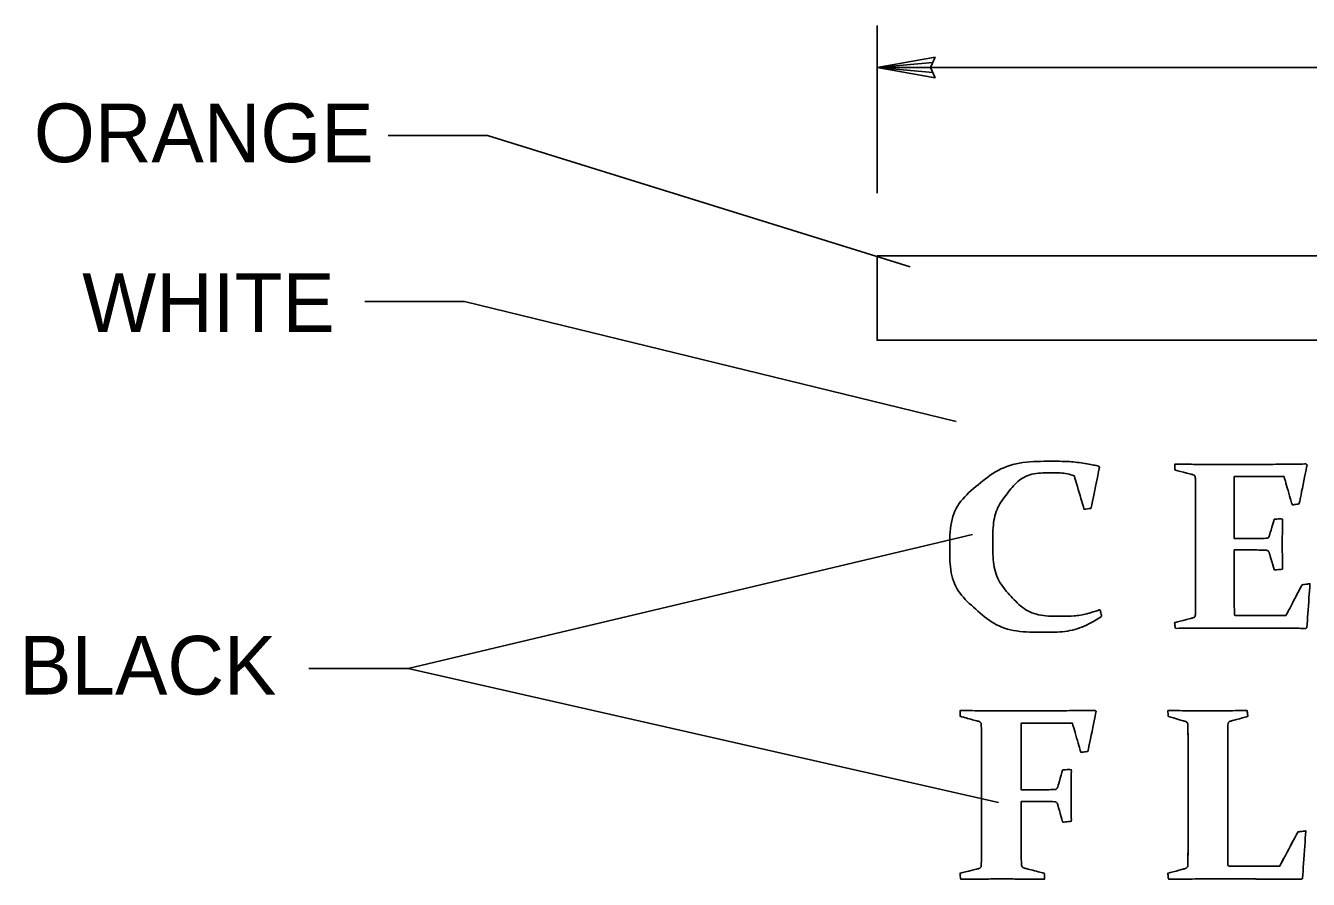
# Model space of a CAD drawing. Extents: x 60714 to 61343, y 7599 to 7998.
# Drawn here: x 60919.9 to 60981.2, y 7950.5 to 7991.3 of the extents above; entities that cross this region are included whole.
import ezdxf

# ---------------------------------------------------------------- set-up
doc = ezdxf.new("R2010")
doc.units = 0
for name, color, linetype in [('2', 7, 'Continuous'), ('21', 7, 'Continuous'), ('Default', 7, 'Continuous'), ('SignPanel', 7, 'Continuous')]:
    doc.layers.add(name, color=color, linetype=linetype)

# ---------------------------------------------------------------- blocks, each defined once
blk = doc.blocks.new('block 5')
at = {"layer": 'Default'}
for points in [[(397.18, -471.19), (397.18, -471.19), (394.77, -471.59), (394.77, -471.59), (394.77, -471.59), (391.44, -459.01), (391.44, -459.01), (389.13, -458.28), (386.63, -457.91), (383.94, -457.91), (377.49, -457.91), (372.49, -460.33), (368.96, -465.17), (365.42, -470), (363.66, -476.33), (363.66, -484.16), (363.66, -492.52), (365.74, -499.18), (369.9, -504.14), (374.06, -509.11), (379.84, -511.59), (387.23, -511.59), (391.35, -511.59), (395.69, -510.76), (400.24, -509.09), (400.24, -509.09), (400.81, -511.59), (400.81, -511.59), (394.97, -515.56), (388.37, -517.55), (381.01, -517.55), (371.46, -517.55), (363.74, -514.67), (357.85, -508.92), (351.96, -503.16), (349.02, -495.58), (349.02, -486.18), (349.02, -476.16), (352.25, -468.23), (358.71, -462.38), (365.16, -456.54), (373.59, -453.62), (383.99, -453.62), (389.13, -453.62), (394.39, -454.22), (399.76, -455.42), (399.76, -455.42), (400.03, -455.86), (400.03, -455.86), (400.03, -455.86), (397.18, -471.19), (397.18, -471.19)], [(397.18, -471.19), (397.18, -471.19), (394.77, -471.59), (394.77, -471.59), (394.77, -471.59), (391.44, -459.01), (391.44, -459.01), (389.13, -458.28), (386.63, -457.91), (383.94, -457.91), (377.49, -457.91), (372.49, -460.33), (368.96, -465.17), (365.42, -470), (363.66, -476.33), (363.66, -484.16), (363.66, -492.52), (365.74, -499.18), (369.9, -504.14), (374.06, -509.11), (379.84, -511.59), (387.23, -511.59), (391.35, -511.59), (395.69, -510.76), (400.24, -509.09), (400.24, -509.09), (400.81, -511.59), (400.81, -511.59), (394.97, -515.56), (388.37, -517.55), (381.01, -517.55), (371.46, -517.55), (363.74, -514.67), (357.85, -508.92), (351.96, -503.16), (349.02, -495.58), (349.02, -486.18), (349.02, -476.16), (352.25, -468.23), (358.71, -462.38), (365.16, -456.54), (373.59, -453.62), (383.99, -453.62), (389.13, -453.62), (394.39, -454.22), (399.76, -455.42), (399.76, -455.42), (400.03, -455.86), (400.03, -455.86), (400.03, -455.86), (397.18, -471.19), (397.18, -471.19)], [(437.3, -454.8), (437.3, -454.8), (448.38, -454.8), (448.38, -454.8), (455.48, -454.8), (462.84, -454.75), (470.47, -454.63), (470.47, -454.63), (470.77, -454.98), (470.77, -454.98), (470.77, -454.98), (468.06, -469.57), (468.06, -469.57), (468.06, -469.57), (465.69, -469.92), (465.69, -469.92), (465.69, -469.92), (462.89, -459.27), (462.89, -459.27), (462.89, -459.27), (445.93, -459.27), (445.93, -459.27), (445.93, -459.27), (445.93, -482.54), (445.93, -482.54), (445.93, -482.54), (448.3, -482.54), (448.3, -482.54), (450.84, -482.54), (453.57, -482.51), (456.49, -482.45), (457.25, -482.42), (457.75, -482.03), (457.98, -481.27), (457.98, -481.27), (459.56, -475.27), (459.56, -475.27), (459.56, -475.27), (462.45, -475.13), (462.45, -475.13), (462.36, -479.37), (462.32, -482.54), (462.32, -484.64), (462.32, -486.69), (462.36, -489.81), (462.45, -494.02), (462.45, -494.02), (459.56, -494.24), (459.56, -494.24), (459.56, -494.24), (457.94, -488.06), (457.94, -488.06), (457.7, -487.27), (457.25, -486.86), (456.58, -486.83), (453.6, -486.78), (450.82, -486.75), (448.25, -486.75), (448.25, -486.75), (445.93, -486.75), (445.93, -486.75), (445.93, -486.75), (445.93, -501.78), (445.93, -501.78), (445.93, -504.99), (445.96, -508.17), (446.02, -511.33), (446.02, -511.33), (463.54, -511.33), (463.54, -511.33), (463.54, -511.33), (469.06, -499.8), (469.06, -499.8), (469.06, -499.8), (471.74, -499.41), (471.74, -499.41), (471.74, -499.41), (470.69, -515.8), (470.69, -515.8), (470.69, -515.8), (470.38, -516.1), (470.38, -516.1), (463.11, -516.02), (456.02, -515.97), (449.13, -515.97), (449.13, -515.97), (437.52, -515.97), (437.52, -515.97), (433.75, -515.97), (429.86, -516.02), (425.86, -516.1), (425.86, -516.1), (425.64, -513.91), (425.64, -513.91), (425.64, -513.91), (431.51, -512.29), (431.51, -512.29), (432.24, -512.09), (432.64, -511.64), (432.7, -510.93), (432.73, -509.77), (432.75, -508.46), (432.76, -507.01), (432.78, -505.57), (432.78, -503.97), (432.78, -502.21), (432.78, -502.21), (432.78, -467.29), (432.78, -467.29), (432.78, -465.83), (432.78, -464.5), (432.76, -463.3), (432.75, -462.11), (432.73, -461.01), (432.7, -460.02), (432.67, -459.26), (432.32, -458.78), (431.64, -458.57), (431.64, -458.57), (425.77, -456.86), (425.77, -456.86), (425.77, -456.86), (425.64, -454.63), (425.64, -454.63), (429.73, -454.75), (433.62, -454.8), (437.3, -454.8)], [(437.3, -454.8), (437.3, -454.8), (448.38, -454.8), (448.38, -454.8), (455.48, -454.8), (462.84, -454.75), (470.47, -454.63), (470.47, -454.63), (470.77, -454.98), (470.77, -454.98), (470.77, -454.98), (468.06, -469.57), (468.06, -469.57), (468.06, -469.57), (465.69, -469.92), (465.69, -469.92), (465.69, -469.92), (462.89, -459.27), (462.89, -459.27), (462.89, -459.27), (445.93, -459.27), (445.93, -459.27), (445.93, -459.27), (445.93, -482.54), (445.93, -482.54), (445.93, -482.54), (448.3, -482.54), (448.3, -482.54), (450.84, -482.54), (453.57, -482.51), (456.49, -482.45), (457.25, -482.42), (457.75, -482.03), (457.98, -481.27), (457.98, -481.27), (459.56, -475.27), (459.56, -475.27), (459.56, -475.27), (462.45, -475.13), (462.45, -475.13), (462.36, -479.37), (462.32, -482.54), (462.32, -484.64), (462.32, -486.69), (462.36, -489.81), (462.45, -494.02), (462.45, -494.02), (459.56, -494.24), (459.56, -494.24), (459.56, -494.24), (457.94, -488.06), (457.94, -488.06), (457.7, -487.27), (457.25, -486.86), (456.58, -486.83), (453.6, -486.78), (450.82, -486.75), (448.25, -486.75), (448.25, -486.75), (445.93, -486.75), (445.93, -486.75), (445.93, -486.75), (445.93, -501.78), (445.93, -501.78), (445.93, -504.99), (445.96, -508.17), (446.02, -511.33), (446.02, -511.33), (463.54, -511.33), (463.54, -511.33), (463.54, -511.33), (469.06, -499.8), (469.06, -499.8), (469.06, -499.8), (471.74, -499.41), (471.74, -499.41), (471.74, -499.41), (470.69, -515.8), (470.69, -515.8), (470.69, -515.8), (470.38, -516.1), (470.38, -516.1), (463.11, -516.02), (456.02, -515.97), (449.13, -515.97), (449.13, -515.97), (437.52, -515.97), (437.52, -515.97), (433.75, -515.97), (429.86, -516.02), (425.86, -516.1), (425.86, -516.1), (425.64, -513.91), (425.64, -513.91), (425.64, -513.91), (431.51, -512.29), (431.51, -512.29), (432.24, -512.09), (432.64, -511.64), (432.7, -510.93), (432.73, -509.77), (432.75, -508.46), (432.76, -507.01), (432.78, -505.57), (432.78, -503.97), (432.78, -502.21), (432.78, -502.21), (432.78, -467.29), (432.78, -467.29), (432.78, -465.83), (432.78, -464.5), (432.76, -463.3), (432.75, -462.11), (432.73, -461.01), (432.7, -460.02), (432.67, -459.26), (432.32, -458.78), (431.64, -458.57), (431.64, -458.57), (425.77, -456.86), (425.77, -456.86), (425.77, -456.86), (425.64, -454.63), (425.64, -454.63), (429.73, -454.75), (433.62, -454.8), (437.3, -454.8)]]:
    blk.add_open_spline(points, degree=3, dxfattribs=at)
blk = doc.blocks.new('block 6')
at = {"layer": 'Default'}
blk.add_open_spline([(836.58, -467.12), (836.58, -467.12), (836.58, -501.78), (836.58, -501.78), (836.58, -504.99), (836.61, -508.17), (836.67, -511.33), (836.67, -511.33), (853.81, -511.33), (853.81, -511.33), (853.81, -511.33), (859.81, -498.88), (859.81, -498.88), (859.81, -498.88), (862.48, -498.49), (862.48, -498.49), (862.48, -498.49), (861.39, -515.8), (861.39, -515.8), (861.39, -515.8), (861.08, -516.1), (861.08, -516.1), (853.86, -516.02), (846.81, -515.97), (839.91, -515.97), (839.91, -515.97), (829.05, -515.97), (829.05, -515.97), (824.7, -515.97), (820.66, -516.02), (816.95, -516.1), (816.95, -516.1), (816.74, -513.91), (816.74, -513.91), (816.74, -513.91), (822.17, -512.29), (822.17, -512.29), (822.9, -512.09), (823.29, -511.64), (823.35, -510.93), (823.38, -509.77), (823.4, -508.46), (823.42, -507.01), (823.43, -505.57), (823.44, -503.97), (823.44, -502.21), (823.44, -502.21), (823.44, -467.29), (823.44, -467.29), (823.44, -465.83), (823.43, -464.5), (823.42, -463.3), (823.4, -462.11), (823.38, -461.01), (823.35, -460.02), (823.32, -459.26), (822.97, -458.78), (822.3, -458.57), (822.3, -458.57), (816.87, -456.86), (816.87, -456.86), (816.87, -456.86), (816.74, -454.63), (816.74, -454.63), (820.5, -454.75), (824.86, -454.8), (829.79, -454.8), (834.88, -454.8), (839.29, -454.75), (843.03, -454.63), (843.03, -454.63), (843.25, -456.86), (843.25, -456.86), (843.25, -456.86), (837.81, -458.48), (837.81, -458.48), (837.11, -458.66), (836.73, -459.1), (836.67, -459.8), (836.64, -460.85), (836.62, -462.35), (836.6, -464.29), (836.59, -466.23), (836.58, -467.17), (836.58, -467.12)], degree=3, dxfattribs=at)
blk.add_open_spline([(836.58, -467.12), (836.58, -467.12), (836.58, -501.78), (836.58, -501.78), (836.58, -504.99), (836.61, -508.17), (836.67, -511.33), (836.67, -511.33), (853.81, -511.33), (853.81, -511.33), (853.81, -511.33), (859.81, -498.88), (859.81, -498.88), (859.81, -498.88), (862.48, -498.49), (862.48, -498.49), (862.48, -498.49), (861.39, -515.8), (861.39, -515.8), (861.39, -515.8), (861.08, -516.1), (861.08, -516.1), (853.86, -516.02), (846.81, -515.97), (839.91, -515.97), (839.91, -515.97), (829.05, -515.97), (829.05, -515.97), (824.7, -515.97), (820.66, -516.02), (816.95, -516.1), (816.95, -516.1), (816.74, -513.91), (816.74, -513.91), (816.74, -513.91), (822.17, -512.29), (822.17, -512.29), (822.9, -512.09), (823.29, -511.64), (823.35, -510.93), (823.38, -509.77), (823.4, -508.46), (823.42, -507.01), (823.43, -505.57), (823.44, -503.97), (823.44, -502.21), (823.44, -502.21), (823.44, -467.29), (823.44, -467.29), (823.44, -465.83), (823.43, -464.5), (823.42, -463.3), (823.4, -462.11), (823.38, -461.01), (823.35, -460.02), (823.32, -459.26), (822.97, -458.78), (822.3, -458.57), (822.3, -458.57), (816.87, -456.86), (816.87, -456.86), (816.87, -456.86), (816.74, -454.63), (816.74, -454.63), (820.5, -454.75), (824.86, -454.8), (829.79, -454.8), (834.88, -454.8), (839.29, -454.75), (843.03, -454.63), (843.03, -454.63), (843.25, -456.86), (843.25, -456.86), (843.25, -456.86), (837.81, -458.48), (837.81, -458.48), (837.11, -458.66), (836.73, -459.1), (836.67, -459.8), (836.64, -460.85), (836.62, -462.35), (836.6, -464.29), (836.59, -466.23), (836.58, -467.17), (836.58, -467.12)], degree=3, dxfattribs=at)

msp = doc.modelspace()

# ---------------------------------------------------------------- linework, layer by layer
at = {"layer": '2'}
for p, q in [((60960.568, 7983.258), (60960.568, 7991.258)), ((60960.568, 7989.258), (61040.577, 7989.258)), ((60937.206, 7986.017), (60941.956, 7986.017)), ((60962.148, 7979.738), (60941.956, 7986.017)), ((60936.099, 7978.08), (60940.849, 7978.08)), ((60940.849, 7978.08), (60964.348, 7972.35)), ((60938.169, 7960.541), (60965.128, 7966.944)), ((60933.419, 7960.541), (60938.169, 7960.541)), ((60938.169, 7960.541), (60966.372, 7954.138))]:
    msp.add_line(p, q, dxfattribs=at)
at = {"layer": '21'}
for p, q in [((60960.568, 7989.258), (60963.337, 7989.746)), ((60960.568, 7989.258), (60963.224, 7989.49)), ((60963.125, 7989.258), (60963.337, 7989.746)), ((60960.568, 7989.258), (60963.336, 7988.769)), ((60960.568, 7989.258), (60963.226, 7989.026)), ((60963.336, 7988.769), (60963.125, 7989.258))]:
    msp.add_line(p, q, dxfattribs=at)
at = {"layer": 'SignPanel'}
msp.add_lwpolyline([(60960.568, 7980.258), (61040.577, 7980.258), (61040.577, 7976.231), (60960.568, 7976.231), (60960.568, 7980.258)], dxfattribs=at)
for points in [[(60967.45, 7954.194), (60967.45, 7954.194), (60967.45, 7952.295), (60967.45, 7952.295), (60967.45, 7951.842), (60967.455, 7951.472), (60967.463, 7951.184), (60967.467, 7951.091), (60967.522, 7951.03), (60967.627, 7950.999), (60967.627, 7950.999), (60968.555, 7950.758), (60968.555, 7950.758), (60968.555, 7950.758), (60968.574, 7950.47), (60968.574, 7950.47), (60967.922, 7950.482), (60967.24, 7950.487), (60966.529, 7950.487), (60965.8, 7950.487), (60965.144, 7950.482), (60964.559, 7950.47), (60964.559, 7950.47), (60964.527, 7950.758), (60964.527, 7950.758), (60964.527, 7950.758), (60965.373, 7950.971), (60965.373, 7950.971), (60965.483, 7951.001), (60965.54, 7951.061), (60965.544, 7951.149), (60965.552, 7951.46), (60965.556, 7951.842), (60965.556, 7952.295), (60965.556, 7952.295), (60965.556, 7956.882), (60965.556, 7956.882), (60965.556, 7957.073), (60965.555, 7957.248), (60965.553, 7957.405), (60965.551, 7957.563), (60965.548, 7957.707), (60965.544, 7957.837), (60965.54, 7957.937), (60965.489, 7958), (60965.392, 7958.027), (60965.392, 7958.027), (60964.546, 7958.251), (60964.546, 7958.251), (60964.546, 7958.251), (60964.527, 7958.545), (60964.527, 7958.545), (60965.116, 7958.53), (60965.676, 7958.522), (60966.206, 7958.522), (60966.206, 7958.522), (60967.804, 7958.522), (60967.804, 7958.522), (60968.827, 7958.522), (60969.888, 7958.53), (60970.986, 7958.545), (60970.986, 7958.545), (60971.03, 7958.499), (60971.03, 7958.499), (60971.03, 7958.499), (60970.639, 7956.582), (60970.639, 7956.582), (60970.639, 7956.582), (60970.298, 7956.536), (60970.298, 7956.536), (60970.298, 7956.536), (60969.894, 7957.935), (60969.894, 7957.935), (60969.894, 7957.935), (60967.45, 7957.935), (60967.45, 7957.935), (60967.45, 7957.935), (60967.45, 7954.746), (60967.45, 7954.746), (60967.45, 7954.746), (60967.81, 7954.746), (60967.81, 7954.746), (60968.181, 7954.746), (60968.574, 7954.75), (60968.991, 7954.758), (60969.105, 7954.762), (60969.176, 7954.814), (60969.206, 7954.913), (60969.206, 7954.913), (60969.433, 7955.702), (60969.433, 7955.702), (60969.433, 7955.702), (60969.85, 7955.719), (60969.85, 7955.719), (60969.837, 7955.163), (60969.831, 7954.746), (60969.831, 7954.47), (60969.831, 7954.202), (60969.837, 7953.791), (60969.85, 7953.238), (60969.85, 7953.238), (60969.433, 7953.204), (60969.433, 7953.204), (60969.433, 7953.204), (60969.199, 7954.021), (60969.199, 7954.021), (60969.17, 7954.121), (60969.105, 7954.175), (60969.004, 7954.182), (60968.578, 7954.19), (60968.179, 7954.194), (60967.804, 7954.194), (60967.804, 7954.194), (60967.45, 7954.194), (60967.45, 7954.194)], [(60967.45, 7954.194), (60967.45, 7954.194), (60967.45, 7952.295), (60967.45, 7952.295), (60967.45, 7951.842), (60967.455, 7951.472), (60967.463, 7951.184), (60967.467, 7951.091), (60967.522, 7951.03), (60967.627, 7950.999), (60967.627, 7950.999), (60968.555, 7950.758), (60968.555, 7950.758), (60968.555, 7950.758), (60968.574, 7950.47), (60968.574, 7950.47), (60967.922, 7950.482), (60967.24, 7950.487), (60966.529, 7950.487), (60965.8, 7950.487), (60965.144, 7950.482), (60964.559, 7950.47), (60964.559, 7950.47), (60964.527, 7950.758), (60964.527, 7950.758), (60964.527, 7950.758), (60965.373, 7950.971), (60965.373, 7950.971), (60965.483, 7951.001), (60965.54, 7951.061), (60965.544, 7951.149), (60965.552, 7951.46), (60965.556, 7951.842), (60965.556, 7952.295), (60965.556, 7952.295), (60965.556, 7956.882), (60965.556, 7956.882), (60965.556, 7957.073), (60965.555, 7957.248), (60965.553, 7957.405), (60965.551, 7957.563), (60965.548, 7957.707), (60965.544, 7957.837), (60965.54, 7957.937), (60965.489, 7958), (60965.392, 7958.027), (60965.392, 7958.027), (60964.546, 7958.251), (60964.546, 7958.251), (60964.546, 7958.251), (60964.527, 7958.545), (60964.527, 7958.545), (60965.116, 7958.53), (60965.676, 7958.522), (60966.206, 7958.522), (60966.206, 7958.522), (60967.804, 7958.522), (60967.804, 7958.522), (60968.827, 7958.522), (60969.888, 7958.53), (60970.986, 7958.545), (60970.986, 7958.545), (60971.03, 7958.499), (60971.03, 7958.499), (60971.03, 7958.499), (60970.639, 7956.582), (60970.639, 7956.582), (60970.639, 7956.582), (60970.298, 7956.536), (60970.298, 7956.536), (60970.298, 7956.536), (60969.894, 7957.935), (60969.894, 7957.935), (60969.894, 7957.935), (60967.45, 7957.935), (60967.45, 7957.935), (60967.45, 7957.935), (60967.45, 7954.746), (60967.45, 7954.746), (60967.45, 7954.746), (60967.81, 7954.746), (60967.81, 7954.746), (60968.181, 7954.746), (60968.574, 7954.75), (60968.991, 7954.758), (60969.105, 7954.762), (60969.176, 7954.814), (60969.206, 7954.913), (60969.206, 7954.913), (60969.433, 7955.702), (60969.433, 7955.702), (60969.433, 7955.702), (60969.85, 7955.719), (60969.85, 7955.719), (60969.837, 7955.163), (60969.831, 7954.746), (60969.831, 7954.47), (60969.831, 7954.202), (60969.837, 7953.791), (60969.85, 7953.238), (60969.85, 7953.238), (60969.433, 7953.204), (60969.433, 7953.204), (60969.433, 7953.204), (60969.199, 7954.021), (60969.199, 7954.021), (60969.17, 7954.121), (60969.105, 7954.175), (60969.004, 7954.182), (60968.578, 7954.19), (60968.179, 7954.194), (60967.804, 7954.194), (60967.804, 7954.194), (60967.45, 7954.194), (60967.45, 7954.194)], [(60977.316, 7956.905), (60977.316, 7956.905), (60977.316, 7952.352), (60977.316, 7952.352), (60977.316, 7951.93), (60977.32, 7951.512), (60977.329, 7951.097), (60977.329, 7951.097), (60979.798, 7951.097), (60979.798, 7951.097), (60979.798, 7951.097), (60980.662, 7952.732), (60980.662, 7952.732), (60980.662, 7952.732), (60981.047, 7952.784), (60981.047, 7952.784), (60981.047, 7952.784), (60980.89, 7950.51), (60980.89, 7950.51), (60980.89, 7950.51), (60980.845, 7950.47), (60980.845, 7950.47), (60979.806, 7950.482), (60978.789, 7950.487), (60977.796, 7950.487), (60977.796, 7950.487), (60976.23, 7950.487), (60976.23, 7950.487), (60975.603, 7950.487), (60975.022, 7950.482), (60974.488, 7950.47), (60974.488, 7950.47), (60974.456, 7950.758), (60974.456, 7950.758), (60974.456, 7950.758), (60975.239, 7950.971), (60975.239, 7950.971), (60975.344, 7950.998), (60975.401, 7951.057), (60975.409, 7951.149), (60975.414, 7951.303), (60975.417, 7951.474), (60975.419, 7951.664), (60975.421, 7951.854), (60975.422, 7952.064), (60975.422, 7952.295), (60975.422, 7952.295), (60975.422, 7956.882), (60975.422, 7956.882), (60975.422, 7957.073), (60975.421, 7957.248), (60975.419, 7957.405), (60975.417, 7957.563), (60975.414, 7957.707), (60975.409, 7957.837), (60975.405, 7957.937), (60975.355, 7958), (60975.258, 7958.027), (60975.258, 7958.027), (60974.475, 7958.251), (60974.475, 7958.251), (60974.475, 7958.251), (60974.456, 7958.545), (60974.456, 7958.545), (60974.999, 7958.53), (60975.626, 7958.522), (60976.338, 7958.522), (60977.07, 7958.522), (60977.706, 7958.53), (60978.244, 7958.545), (60978.244, 7958.545), (60978.276, 7958.251), (60978.276, 7958.251), (60978.276, 7958.251), (60977.493, 7958.038), (60977.493, 7958.038), (60977.392, 7958.015), (60977.337, 7957.958), (60977.329, 7957.866), (60977.325, 7957.728), (60977.321, 7957.531), (60977.319, 7957.276), (60977.317, 7957.021), (60977.316, 7956.897), (60977.316, 7956.905)], [(60977.316, 7956.905), (60977.316, 7956.905), (60977.316, 7952.352), (60977.316, 7952.352), (60977.316, 7951.93), (60977.32, 7951.512), (60977.329, 7951.097), (60977.329, 7951.097), (60979.798, 7951.097), (60979.798, 7951.097), (60979.798, 7951.097), (60980.662, 7952.732), (60980.662, 7952.732), (60980.662, 7952.732), (60981.047, 7952.784), (60981.047, 7952.784), (60981.047, 7952.784), (60980.89, 7950.51), (60980.89, 7950.51), (60980.89, 7950.51), (60980.845, 7950.47), (60980.845, 7950.47), (60979.806, 7950.482), (60978.789, 7950.487), (60977.796, 7950.487), (60977.796, 7950.487), (60976.23, 7950.487), (60976.23, 7950.487), (60975.603, 7950.487), (60975.022, 7950.482), (60974.488, 7950.47), (60974.488, 7950.47), (60974.456, 7950.758), (60974.456, 7950.758), (60974.456, 7950.758), (60975.239, 7950.971), (60975.239, 7950.971), (60975.344, 7950.998), (60975.401, 7951.057), (60975.409, 7951.149), (60975.414, 7951.303), (60975.417, 7951.474), (60975.419, 7951.664), (60975.421, 7951.854), (60975.422, 7952.064), (60975.422, 7952.295), (60975.422, 7952.295), (60975.422, 7956.882), (60975.422, 7956.882), (60975.422, 7957.073), (60975.421, 7957.248), (60975.419, 7957.405), (60975.417, 7957.563), (60975.414, 7957.707), (60975.409, 7957.837), (60975.405, 7957.937), (60975.355, 7958), (60975.258, 7958.027), (60975.258, 7958.027), (60974.475, 7958.251), (60974.475, 7958.251), (60974.475, 7958.251), (60974.456, 7958.545), (60974.456, 7958.545), (60974.999, 7958.53), (60975.626, 7958.522), (60976.338, 7958.522), (60977.07, 7958.522), (60977.706, 7958.53), (60978.244, 7958.545), (60978.244, 7958.545), (60978.276, 7958.251), (60978.276, 7958.251), (60978.276, 7958.251), (60977.493, 7958.038), (60977.493, 7958.038), (60977.392, 7958.015), (60977.337, 7957.958), (60977.329, 7957.866), (60977.325, 7957.728), (60977.321, 7957.531), (60977.319, 7957.276), (60977.317, 7957.021), (60977.316, 7956.897), (60977.316, 7956.905)]]:
    msp.add_open_spline(points, degree=3, dxfattribs=at)

# ---------------------------------------------------------------- block references
for name, p, xscale, yscale, rotation in [('block 5', (60915.109, 8028.418), 0.14019599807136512, 0.1278006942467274, -6.923017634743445e-08), ('block 6', (60856.795, 8018.26), 0.14406434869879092, 0.13134966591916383, -6.922538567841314e-08)]:
    msp.add_blockref(name, p, dxfattribs=dict(at, xscale=xscale, yscale=yscale, rotation=rotation))

# ---------------------------------------------------------------- texts
at = {"layer": '2'}
for s, p in [('ORANGE', (60920.286, 7984.735)), ('WHITE', (60922.594, 7976.624)), ('BLACK', (60919.584, 7959.301))]:
    msp.add_text(s, height=2.8, dxfattribs=at).set_placement(p)

doc.saveas('drawing.dxf')
